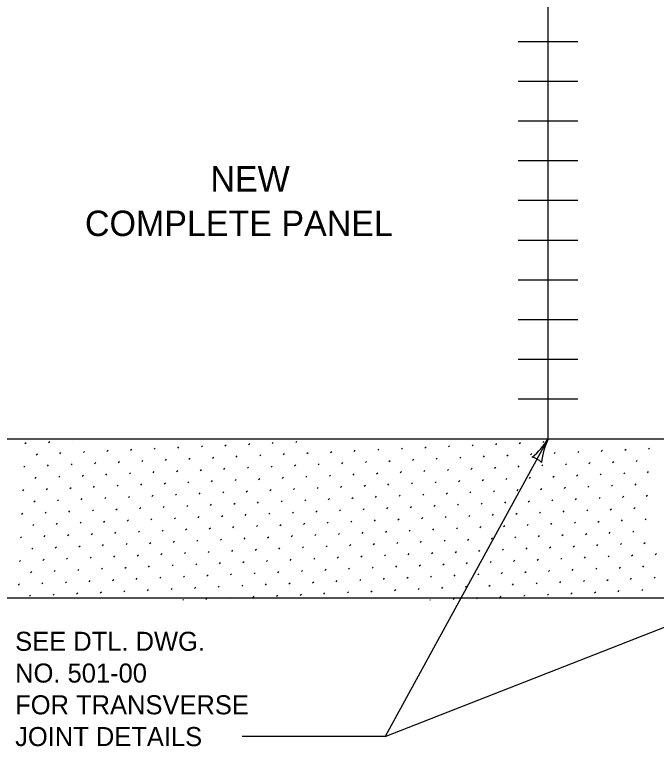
# Model space of a CAD drawing. Extents: x 49991.4 to 50021, y 49987.6 to 50011.4.
# Drawn here: x 50002.506 to 50004.526, y 49993.823 to 49996.127 of the extents above; entities that cross this region are included whole.
import ezdxf

# ---------------------------------------------------------------- set-up
doc = ezdxf.new("R2010")
doc.units = 0
for name, color, linetype in [('Level 1', 7, 'Continuous'), ('Level 10', 7, 'Continuous'), ('Level 2', 7, 'Continuous'), ('Level 3', 7, 'Continuous'), ('Level 4', 7, 'Continuous')]:
    doc.layers.add(name, color=color, linetype=linetype)

msp = doc.modelspace()

# ---------------------------------------------------------------- linework, layer by layer
at = {"layer": 'Level 1'}
for p, q in [((50004.1848, 49997.7903), (50004.1848, 49994.7903)), ((50007.9348, 49994.7903), (50002.3098, 49994.7903)), ((50015.1301, 49994.2903), (50001.3364, 49994.2903))]:
    msp.add_line(p, q, dxfattribs=at)
at = {"layer": 'Level 10'}
for p, q in [((50002.5389, 49994.7767), (50002.5424, 49994.7803)), ((50002.6131, 49994.7803), (50002.6167, 49994.7838)), ((50002.6874, 49994.7838), (50002.6874, 49994.7838)), ((50003.0198, 49994.7626), (50003.0233, 49994.7662)), ((50003.094, 49994.7662), (50003.0975, 49994.7697)), ((50003.1683, 49994.7697), (50003.1718, 49994.7733)), ((50003.2425, 49994.7733), (50003.2461, 49994.7768)), ((50003.3168, 49994.7768), (50003.3203, 49994.7804)), ((50003.391, 49994.7804), (50003.3945, 49994.7838)), ((50003.7976, 49994.7627), (50003.8012, 49994.7663)), ((50003.8719, 49994.7663), (50003.8754, 49994.7698)), ((50003.9462, 49994.7698), (50003.9497, 49994.7733)), ((50004.0204, 49994.7733), (50004.0239, 49994.7769)), ((50004.0947, 49994.7769), (50004.0982, 49994.7804)), ((50004.1689, 49994.7804), (50004.1723, 49994.7838)), ((50002.5742, 49994.7414), (50002.5778, 49994.7449)), ((50002.6485, 49994.7449), (50002.652, 49994.7485)), ((50002.7227, 49994.7485), (50002.7263, 49994.752)), ((50002.797, 49994.752), (50002.8005, 49994.7556)), ((50002.8713, 49994.7556), (50002.8748, 49994.7591)), ((50002.9455, 49994.7591), (50002.949, 49994.7626)), ((50003.3521, 49994.7415), (50003.3557, 49994.745)), ((50003.4264, 49994.745), (50003.4299, 49994.7485)), ((50003.5006, 49994.7485), (50003.5042, 49994.7521)), ((50003.5749, 49994.7521), (50003.5784, 49994.7556)), ((50003.6491, 49994.7556), (50003.6527, 49994.7592)), ((50003.7234, 49994.7592), (50003.7269, 49994.7627)), ((50004.13, 49994.7415), (50004.1336, 49994.7451)), ((50004.2043, 49994.7451), (50004.2078, 49994.7486)), ((50004.2785, 49994.7486), (50004.2821, 49994.7522)), ((50004.3528, 49994.7522), (50004.3563, 49994.7557)), ((50004.427, 49994.7557), (50004.4306, 49994.7592)), ((50004.5013, 49994.7592), (50004.5048, 49994.7628)), ((50002.8324, 49994.7167), (50002.8359, 49994.7202)), ((50002.9066, 49994.7202), (50002.9101, 49994.7237)), ((50002.9809, 49994.7237), (50002.9844, 49994.7273)), ((50003.0551, 49994.7273), (50003.0587, 49994.7308)), ((50003.1294, 49994.7308), (50003.1329, 49994.7344)), ((50003.2036, 49994.7344), (50003.2072, 49994.7379)), ((50003.2779, 49994.7379), (50003.2814, 49994.7415)), ((50003.6102, 49994.7167), (50003.6138, 49994.7203)), ((50003.6845, 49994.7203), (50003.688, 49994.7238)), ((50003.7587, 49994.7238), (50003.7623, 49994.7274)), ((50003.833, 49994.7274), (50003.8365, 49994.7309)), ((50003.9073, 49994.7309), (50003.9108, 49994.7344)), ((50003.9815, 49994.7344), (50003.985, 49994.738)), ((50004.0558, 49994.738), (50004.0593, 49994.7415)), ((50004.3881, 49994.7168), (50004.3917, 49994.7203)), ((50004.4624, 49994.7203), (50004.4659, 49994.7239)), ((50002.5353, 49994.7025), (50002.5389, 49994.706)), ((50002.6096, 49994.706), (50002.6131, 49994.7096)), ((50002.6838, 49994.7096), (50002.6874, 49994.7131)), ((50002.7581, 49994.7131), (50002.7616, 49994.7167)), ((50003.1647, 49994.6955), (50003.1683, 49994.699)), ((50003.239, 49994.699), (50003.2425, 49994.7026)), ((50003.3132, 49994.7026), (50003.3168, 49994.7061)), ((50003.3875, 49994.7061), (50003.391, 49994.7096)), ((50003.4617, 49994.7096), (50003.4653, 49994.7132)), ((50003.536, 49994.7132), (50003.5395, 49994.7167)), ((50003.9426, 49994.6955), (50003.9461, 49994.6991)), ((50004.0169, 49994.6991), (50004.0204, 49994.7026)), ((50004.0911, 49994.7026), (50004.0947, 49994.7062)), ((50004.1654, 49994.7062), (50004.1689, 49994.7097)), ((50004.2396, 49994.7097), (50004.2432, 49994.7133)), ((50004.3139, 49994.7133), (50004.3174, 49994.7168)), ((50002.645, 49994.6707), (50002.6485, 49994.6742)), ((50002.7192, 49994.6742), (50002.7227, 49994.6778)), ((50002.7935, 49994.6778), (50002.797, 49994.6813)), ((50002.8677, 49994.6813), (50002.8712, 49994.6848)), ((50002.942, 49994.6848), (50002.9455, 49994.6884)), ((50003.0162, 49994.6884), (50003.0198, 49994.6919)), ((50003.0905, 49994.6919), (50003.094, 49994.6955)), ((50003.4228, 49994.6707), (50003.4264, 49994.6743)), ((50003.4971, 49994.6743), (50003.5006, 49994.6778)), ((50003.5713, 49994.6778), (50003.5749, 49994.6814)), ((50003.6456, 49994.6814), (50003.6491, 49994.6849)), ((50003.7199, 49994.6849), (50003.7234, 49994.6885)), ((50003.7941, 49994.6885), (50003.7976, 49994.692)), ((50003.8684, 49994.692), (50003.8719, 49994.6955)), ((50004.2007, 49994.6708), (50004.2043, 49994.6744)), ((50004.275, 49994.6744), (50004.2785, 49994.6779)), ((50004.3492, 49994.6779), (50004.3528, 49994.6814)), ((50004.4235, 49994.6814), (50004.427, 49994.685)), ((50004.4977, 49994.685), (50004.5013, 49994.6885)), ((50002.5707, 49994.6671), (50002.5742, 49994.6707)), ((50002.9773, 49994.6495), (50002.9809, 49994.653)), ((50003.0516, 49994.653), (50003.0551, 49994.6566)), ((50003.1258, 49994.6566), (50003.1294, 49994.6601)), ((50003.2001, 49994.6601), (50003.2036, 49994.6637)), ((50003.2743, 49994.6637), (50003.2779, 49994.6672)), ((50003.3486, 49994.6672), (50003.3521, 49994.6707)), ((50003.7552, 49994.6496), (50003.7587, 49994.6531)), ((50003.8295, 49994.6531), (50003.833, 49994.6566)), ((50003.9037, 49994.6566), (50003.9072, 49994.6602)), ((50003.978, 49994.6602), (50003.9815, 49994.6637)), ((50004.0522, 49994.6637), (50004.0558, 49994.6673)), ((50004.1265, 49994.6673), (50004.13, 49994.6708)), ((50002.5318, 49994.6282), (50002.5353, 49994.6318)), ((50002.6061, 49994.6318), (50002.6096, 49994.6353)), ((50002.6803, 49994.6353), (50002.6838, 49994.6389)), ((50002.7546, 49994.6389), (50002.7581, 49994.6424)), ((50002.8288, 49994.6424), (50002.8323, 49994.6459)), ((50002.9031, 49994.646), (50002.9066, 49994.6495)), ((50003.2354, 49994.6248), (50003.239, 49994.6283)), ((50003.3097, 49994.6283), (50003.3132, 49994.6318)), ((50003.3839, 49994.6319), (50003.3875, 49994.6354)), ((50003.4582, 49994.6354), (50003.4617, 49994.6389)), ((50003.5324, 49994.6389), (50003.536, 49994.6425)), ((50003.6067, 49994.6425), (50003.6102, 49994.646)), ((50003.681, 49994.646), (50003.6845, 49994.6496)), ((50004.0133, 49994.6248), (50004.0169, 49994.6284)), ((50004.0876, 49994.6284), (50004.0911, 49994.6319)), ((50004.1618, 49994.6319), (50004.1654, 49994.6355)), ((50004.2361, 49994.6355), (50004.2396, 49994.639)), ((50004.3103, 49994.639), (50004.3139, 49994.6425)), ((50004.3846, 49994.6425), (50004.3881, 49994.6461)), ((50004.4588, 49994.6461), (50004.4624, 49994.6496)), ((50002.7899, 49994.6035), (50002.7934, 49994.607)), ((50002.8642, 49994.6071), (50002.8677, 49994.6106)), ((50002.9384, 49994.6106), (50002.942, 49994.6141)), ((50003.0127, 49994.6141), (50003.0162, 49994.6177)), ((50003.0869, 49994.6177), (50003.0905, 49994.6212)), ((50003.1612, 49994.6212), (50003.1647, 49994.6248)), ((50003.5678, 49994.6036), (50003.5713, 49994.6071)), ((50003.6421, 49994.6071), (50003.6456, 49994.6107)), ((50003.7163, 49994.6107), (50003.7198, 49994.6142)), ((50003.7906, 49994.6142), (50003.7941, 49994.6177)), ((50003.8648, 49994.6178), (50003.8684, 49994.6213)), ((50003.9391, 49994.6213), (50003.9426, 49994.6248)), ((50004.3457, 49994.6037), (50004.3492, 49994.6072)), ((50004.4199, 49994.6072), (50004.4235, 49994.6107)), ((50004.4942, 49994.6107), (50004.4977, 49994.6143)), ((50002.5672, 49994.5929), (50002.5707, 49994.5964)), ((50002.6414, 49994.5964), (50002.6449, 49994.6)), ((50002.7157, 49994.6), (50002.7192, 49994.6035)), ((50003.048, 49994.5788), (50003.0516, 49994.5823)), ((50003.1223, 49994.5823), (50003.1258, 49994.5859)), ((50003.1965, 49994.5859), (50003.2001, 49994.5894)), ((50003.2708, 49994.5894), (50003.2743, 49994.5929)), ((50003.345, 49994.593), (50003.3486, 49994.5965)), ((50003.4193, 49994.5965), (50003.4228, 49994.6)), ((50003.4935, 49994.6), (50003.4971, 49994.6036)), ((50003.8259, 49994.5789), (50003.8295, 49994.5824)), ((50003.9002, 49994.5824), (50003.9037, 49994.5859)), ((50003.9744, 49994.5859), (50003.978, 49994.5895)), ((50004.0487, 49994.5895), (50004.0522, 49994.593)), ((50004.1229, 49994.593), (50004.1265, 49994.5966)), ((50004.1972, 49994.5966), (50004.2007, 49994.6001)), ((50004.2714, 49994.6001), (50004.275, 49994.6036)), ((50002.6025, 49994.5575), (50002.606, 49994.5611)), ((50002.6768, 49994.5611), (50002.6803, 49994.5646)), ((50002.751, 49994.5646), (50002.7546, 49994.5681)), ((50002.8253, 49994.5682), (50002.8288, 49994.5717)), ((50002.8995, 49994.5717), (50002.9031, 49994.5752)), ((50002.9738, 49994.5752), (50002.9773, 49994.5788)), ((50003.3804, 49994.5576), (50003.3839, 49994.5611)), ((50003.4547, 49994.5611), (50003.4582, 49994.5647)), ((50003.5289, 49994.5647), (50003.5324, 49994.5682)), ((50003.6032, 49994.5682), (50003.6067, 49994.5718)), ((50003.6774, 49994.5718), (50003.6809, 49994.5753)), ((50003.7517, 49994.5753), (50003.7552, 49994.5788)), ((50004.1583, 49994.5577), (50004.1618, 49994.5612)), ((50004.2325, 49994.5612), (50004.2361, 49994.5647)), ((50004.3068, 49994.5648), (50004.3103, 49994.5683)), ((50004.381, 49994.5683), (50004.3846, 49994.5718)), ((50004.4553, 49994.5718), (50004.4588, 49994.5754)), ((50002.5283, 49994.554), (50002.5318, 49994.5575)), ((50002.8606, 49994.5328), (50002.8642, 49994.5363)), ((50002.9349, 49994.5363), (50002.9384, 49994.5399)), ((50003.0091, 49994.5399), (50003.0127, 49994.5434)), ((50003.0834, 49994.5434), (50003.0869, 49994.547)), ((50003.1576, 49994.547), (50003.1612, 49994.5505)), ((50003.2319, 49994.5505), (50003.2354, 49994.554)), ((50003.3061, 49994.5541), (50003.3097, 49994.5576)), ((50003.6385, 49994.5329), (50003.642, 49994.5364)), ((50003.7128, 49994.5364), (50003.7163, 49994.5399)), ((50003.787, 49994.54), (50003.7906, 49994.5435)), ((50003.8613, 49994.5435), (50003.8648, 49994.547)), ((50003.9355, 49994.547), (50003.9391, 49994.5506)), ((50004.0098, 49994.5506), (50004.0133, 49994.5541)), ((50004.084, 49994.5541), (50004.0876, 49994.5577)), ((50004.4164, 49994.5329), (50004.4199, 49994.5365)), ((50004.4907, 49994.5365), (50004.4942, 49994.54)), ((50002.5636, 49994.5186), (50002.5671, 49994.5222)), ((50002.6379, 49994.5222), (50002.6414, 49994.5257)), ((50002.7121, 49994.5257), (50002.7157, 49994.5292)), ((50002.7864, 49994.5293), (50002.7899, 49994.5328)), ((50003.193, 49994.5116), (50003.1965, 49994.5152)), ((50003.2672, 49994.5152), (50003.2708, 49994.5187)), ((50003.3415, 49994.5187), (50003.345, 49994.5222)), ((50003.4158, 49994.5222), (50003.4193, 49994.5258)), ((50003.49, 49994.5258), (50003.4935, 49994.5293)), ((50003.5643, 49994.5293), (50003.5678, 49994.5329)), ((50003.8966, 49994.5081), (50003.9002, 49994.5117)), ((50003.9709, 49994.5117), (50003.9744, 49994.5152)), ((50004.0451, 49994.5152), (50004.0487, 49994.5188)), ((50004.1194, 49994.5188), (50004.1229, 49994.5223)), ((50004.1936, 49994.5223), (50004.1972, 49994.5258)), ((50004.2679, 49994.5259), (50004.2714, 49994.5294)), ((50004.3421, 49994.5294), (50004.3457, 49994.5329)), ((50002.6732, 49994.4868), (50002.6768, 49994.4904)), ((50002.7475, 49994.4904), (50002.751, 49994.4939)), ((50002.8217, 49994.4939), (50002.8253, 49994.4974)), ((50002.896, 49994.4974), (50002.8995, 49994.501)), ((50002.9702, 49994.501), (50002.9738, 49994.5045)), ((50003.0445, 49994.5045), (50003.048, 49994.5081)), ((50003.1187, 49994.5081), (50003.1223, 49994.5116)), ((50003.4511, 49994.4869), (50003.4546, 49994.4904)), ((50003.5254, 49994.4904), (50003.5289, 49994.494)), ((50003.5996, 49994.494), (50003.6032, 49994.4975)), ((50003.6739, 49994.4975), (50003.6774, 49994.5011)), ((50003.7481, 49994.5011), (50003.7517, 49994.5046)), ((50003.8224, 49994.5046), (50003.8259, 49994.5081)), ((50004.229, 49994.487), (50004.2325, 49994.4905)), ((50004.3032, 49994.4905), (50004.3068, 49994.494)), ((50004.3775, 49994.494), (50004.381, 49994.4976)), ((50004.4518, 49994.4976), (50004.4553, 49994.5011)), ((50002.5247, 49994.4797), (50002.5282, 49994.4833)), ((50002.599, 49994.4833), (50002.6025, 49994.4868)), ((50002.9313, 49994.4621), (50002.9349, 49994.4656)), ((50003.0056, 49994.4656), (50003.0091, 49994.4692)), ((50003.0798, 49994.4692), (50003.0834, 49994.4727)), ((50003.1541, 49994.4727), (50003.1576, 49994.4763)), ((50003.2283, 49994.4763), (50003.2319, 49994.4798)), ((50003.3026, 49994.4798), (50003.3061, 49994.4833)), ((50003.3769, 49994.4833), (50003.3804, 49994.4869)), ((50003.7092, 49994.4622), (50003.7128, 49994.4657)), ((50003.7835, 49994.4657), (50003.787, 49994.4692)), ((50003.8577, 49994.4692), (50003.8613, 49994.4728)), ((50003.932, 49994.4728), (50003.9355, 49994.4763)), ((50004.0062, 49994.4763), (50004.0098, 49994.4799)), ((50004.0805, 49994.4799), (50004.084, 49994.4834)), ((50004.1547, 49994.4834), (50004.1583, 49994.487)), ((50004.4871, 49994.4622), (50004.4906, 49994.4658)), ((50002.5601, 49994.4444), (50002.5636, 49994.4479)), ((50002.6343, 49994.4479), (50002.6379, 49994.4515)), ((50002.7086, 49994.4515), (50002.7121, 49994.455)), ((50002.7828, 49994.455), (50002.7864, 49994.4585)), ((50002.8571, 49994.4585), (50002.8606, 49994.4621)), ((50003.2637, 49994.4409), (50003.2672, 49994.4444)), ((50003.338, 49994.4444), (50003.3415, 49994.448)), ((50003.4122, 49994.448), (50003.4157, 49994.4515)), ((50003.4865, 49994.4515), (50003.49, 49994.4551)), ((50003.5607, 49994.4551), (50003.5643, 49994.4586)), ((50003.635, 49994.4586), (50003.6385, 49994.4622)), ((50004.0416, 49994.441), (50004.0451, 49994.4445)), ((50004.1158, 49994.4445), (50004.1194, 49994.4481)), ((50004.1901, 49994.4481), (50004.1936, 49994.4516)), ((50004.2644, 49994.4516), (50004.2679, 49994.4551)), ((50004.3386, 49994.4551), (50004.3421, 49994.4587)), ((50004.4129, 49994.4587), (50004.4164, 49994.4622)), ((50002.7439, 49994.4161), (50002.7475, 49994.4196)), ((50002.8182, 49994.4196), (50002.8217, 49994.4232)), ((50002.8924, 49994.4232), (50002.896, 49994.4267)), ((50002.9667, 49994.4267), (50002.9702, 49994.4303)), ((50003.0409, 49994.4303), (50003.0445, 49994.4338)), ((50003.1152, 49994.4338), (50003.1187, 49994.4374)), ((50003.1895, 49994.4374), (50003.193, 49994.4409)), ((50003.5218, 49994.4162), (50003.5254, 49994.4197)), ((50003.5961, 49994.4197), (50003.5996, 49994.4233)), ((50003.6703, 49994.4233), (50003.6739, 49994.4268)), ((50003.7446, 49994.4268), (50003.7481, 49994.4303)), ((50003.8188, 49994.4303), (50003.8224, 49994.4339)), ((50003.8931, 49994.4339), (50003.8966, 49994.4374)), ((50003.9673, 49994.4374), (50003.9709, 49994.441)), ((50004.2997, 49994.4162), (50004.3032, 49994.4198)), ((50004.374, 49994.4198), (50004.3775, 49994.4233)), ((50004.4482, 49994.4233), (50004.4517, 49994.4269)), ((50004.5225, 49994.4269), (50004.526, 49994.4304)), ((50002.5212, 49994.4055), (50002.5247, 49994.409)), ((50002.5954, 49994.409), (50002.599, 49994.4126)), ((50002.6697, 49994.4126), (50002.6732, 49994.4161)), ((50003.0763, 49994.3949), (50003.0798, 49994.3985)), ((50003.1506, 49994.3985), (50003.1541, 49994.402)), ((50003.2248, 49994.402), (50003.2283, 49994.4055)), ((50003.2991, 49994.4055), (50003.3026, 49994.4091)), ((50003.3733, 49994.4091), (50003.3768, 49994.4126)), ((50003.4476, 49994.4126), (50003.4511, 49994.4162)), ((50003.8542, 49994.395), (50003.8577, 49994.3985)), ((50003.9284, 49994.3985), (50003.932, 49994.4021)), ((50004.0027, 49994.4021), (50004.0062, 49994.4056)), ((50004.0769, 49994.4056), (50004.0805, 49994.4092)), ((50004.1512, 49994.4092), (50004.1547, 49994.4127)), ((50004.2255, 49994.4127), (50004.229, 49994.4162)), ((50002.5565, 49994.3701), (50002.5601, 49994.3737)), ((50002.6308, 49994.3737), (50002.6343, 49994.3772)), ((50002.705, 49994.3772), (50002.7086, 49994.3807)), ((50002.7793, 49994.3808), (50002.7828, 49994.3843)), ((50002.8535, 49994.3843), (50002.8571, 49994.3878)), ((50002.9278, 49994.3878), (50002.9313, 49994.3914)), ((50003.002, 49994.3914), (50003.0056, 49994.3949)), ((50003.3344, 49994.3702), (50003.338, 49994.3737)), ((50003.4087, 49994.3737), (50003.4122, 49994.3773)), ((50003.4829, 49994.3773), (50003.4865, 49994.3808)), ((50003.5572, 49994.3808), (50003.5607, 49994.3844)), ((50003.6314, 49994.3844), (50003.635, 49994.3879)), ((50003.7057, 49994.3879), (50003.7092, 49994.3914)), ((50003.7799, 49994.3914), (50003.7835, 49994.395)), ((50004.1123, 49994.3703), (50004.1158, 49994.3738)), ((50004.1866, 49994.3738), (50004.1901, 49994.3773)), ((50004.2608, 49994.3773), (50004.2643, 49994.3809)), ((50004.3351, 49994.3809), (50004.3386, 49994.3844)), ((50004.4093, 49994.3844), (50004.4129, 49994.388)), ((50004.4836, 49994.388), (50004.4871, 49994.3915)), ((50002.8889, 49994.3489), (50002.8924, 49994.3525)), ((50002.9631, 49994.3525), (50002.9667, 49994.356)), ((50003.0374, 49994.356), (50003.0409, 49994.3596)), ((50003.1117, 49994.3596), (50003.1152, 49994.3631)), ((50003.1859, 49994.3631), (50003.1894, 49994.3666)), ((50003.2602, 49994.3667), (50003.2637, 49994.3702)), ((50003.6668, 49994.349), (50003.6703, 49994.3525)), ((50003.741, 49994.3526), (50003.7446, 49994.3561)), ((50003.8153, 49994.3561), (50003.8188, 49994.3596)), ((50003.8895, 49994.3596), (50003.8931, 49994.3632)), ((50003.9638, 49994.3632), (50003.9673, 49994.3667)), ((50004.038, 49994.3667), (50004.0416, 49994.3703)), ((50004.4447, 49994.3491), (50004.4482, 49994.3526)), ((50004.5189, 49994.3526), (50004.5225, 49994.3562)), ((50002.5176, 49994.3312), (50002.5212, 49994.3348)), ((50002.5919, 49994.3348), (50002.5954, 49994.3383)), ((50002.6661, 49994.3383), (50002.6697, 49994.3418)), ((50002.7404, 49994.3419), (50002.7439, 49994.3454)), ((50002.8146, 49994.3454), (50002.8182, 49994.3489)), ((50003.147, 49994.3242), (50003.1505, 49994.3277)), ((50003.2213, 49994.3278), (50003.2248, 49994.3313)), ((50003.2955, 49994.3313), (50003.2991, 49994.3348)), ((50003.3698, 49994.3348), (50003.3733, 49994.3384)), ((50003.444, 49994.3384), (50003.4476, 49994.3419)), ((50003.5183, 49994.3419), (50003.5218, 49994.3455)), ((50003.5925, 49994.3455), (50003.5961, 49994.349)), ((50003.9249, 49994.3243), (50003.9284, 49994.3278)), ((50003.9992, 49994.3278), (50004.0027, 49994.3314)), ((50004.0734, 49994.3314), (50004.0769, 49994.3349)), ((50004.1477, 49994.3349), (50004.1512, 49994.3384)), ((50004.2219, 49994.3385), (50004.2254, 49994.342)), ((50004.2962, 49994.342), (50004.2997, 49994.3455)), ((50004.3704, 49994.3455), (50004.374, 49994.3491)), ((50002.7015, 49994.303), (50002.705, 49994.3065)), ((50002.7757, 49994.3065), (50002.7793, 49994.31)), ((50002.85, 49994.31), (50002.8535, 49994.3136)), ((50002.9243, 49994.3136), (50002.9278, 49994.3171)), ((50002.9985, 49994.3171), (50003.002, 49994.3207)), ((50003.0728, 49994.3207), (50003.0763, 49994.3242)), ((50003.4794, 49994.303), (50003.4829, 49994.3066)), ((50003.5536, 49994.3066), (50003.5572, 49994.3101)), ((50003.6279, 49994.3101), (50003.6314, 49994.3136)), ((50003.7021, 49994.3137), (50003.7057, 49994.3172)), ((50003.7764, 49994.3172), (50003.7799, 49994.3207)), ((50003.8506, 49994.3207), (50003.8542, 49994.3243)), ((50004.2573, 49994.3031), (50004.2608, 49994.3066)), ((50004.3315, 49994.3066), (50004.3351, 49994.3102)), ((50004.4058, 49994.3102), (50004.4093, 49994.3137)), ((50004.48, 49994.3137), (50004.4836, 49994.3173)), ((50002.553, 49994.2959), (50002.5565, 49994.2994)), ((50002.6272, 49994.2994), (50002.6308, 49994.3029)), ((50003.0359, 49994.2838), (50003.0374, 49994.2853)), ((50003.1081, 49994.2853), (50003.1116, 49994.2888)), ((50003.1824, 49994.2889), (50003.1859, 49994.2924)), ((50003.2566, 49994.2924), (50003.2602, 49994.2959)), ((50003.3309, 49994.2959), (50003.3344, 49994.2995)), ((50003.4051, 49994.2995), (50003.4087, 49994.303)), ((50003.8137, 49994.2838), (50003.8153, 49994.2854)), ((50003.886, 49994.2854), (50003.8895, 49994.2889)), ((50003.9603, 49994.2889), (50003.9638, 49994.2925)), ((50004.0345, 49994.2925), (50004.038, 49994.296)), ((50004.1088, 49994.296), (50004.1123, 49994.2995)), ((50004.183, 49994.2996), (50004.1865, 49994.3031))]:
    msp.add_line(p, q, dxfattribs=at)
at = {"layer": 'Level 3'}
for p, q in [((50004.1848, 49994.7903), (50003.6725, 49993.8542)), ((50003.6725, 49993.8542), (50006.0598, 49994.7903)), ((50003.6725, 49993.8542), (50003.2221, 49993.8542))]:
    msp.add_line(p, q, dxfattribs=at)
for centre, radius, start, end in [((50003.9955, 49994.9069), 0.2223, 308.7663, 328.9499), ((50004.3956, 49994.6906), 0.233, 154.1376, 173.3875), ((50004.1244, 49994.6798), 0.0548, 43.4492, 79.1715)]:
    msp.add_arc(centre, radius, start, end, dxfattribs=at)
at = {"layer": 'Level 4'}
for p, q in [((50004.091, 49996.0427), (50004.2785, 49996.0427)), ((50004.091, 49995.9177), (50004.2785, 49995.9177)), ((50004.091, 49995.7927), (50004.2785, 49995.7927)), ((50004.091, 49995.6677), (50004.2785, 49995.6677)), ((50004.091, 49995.5427), (50004.2785, 49995.5427)), ((50004.091, 49995.4177), (50004.2785, 49995.4177)), ((50004.091, 49995.2927), (50004.2785, 49995.2927)), ((50004.091, 49995.1677), (50004.2785, 49995.1677)), ((50004.091, 49995.0427), (50004.2785, 49995.0427)), ((50004.091, 49994.9177), (50004.2785, 49994.9177))]:
    msp.add_line(p, q, dxfattribs=at)

# ---------------------------------------------------------------- texts
at = {"layer": 'Level 2'}
for s, height, p in [('NEW', 0.08, (50003.1225, 49995.5703)), ('COMPLETE PANEL', 0.08, (50002.7277, 49995.4303)), ('SEE DTL. DWG. ', 0.06, (50002.508, 49994.1242)), ('NO. 501-00', 0.06, (50002.508, 49994.0242)), ('FOR TRANSVERSE ', 0.06, (50002.508, 49993.9242)), ('JOINT DETAILS', 0.06, (50002.508, 49993.8242))]:
    msp.add_text(s, height=height, dxfattribs=at).set_placement(p)

doc.saveas('drawing.dxf')
